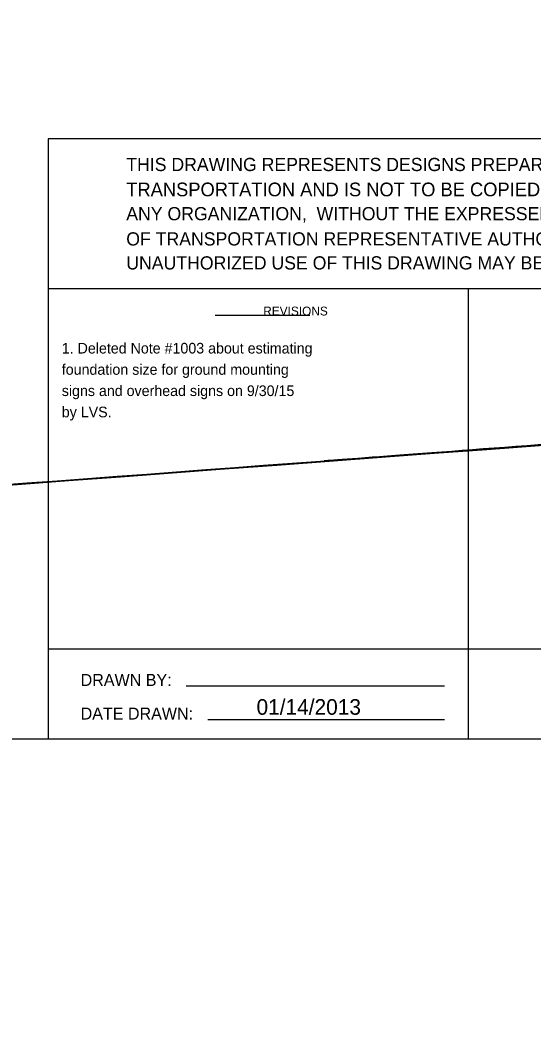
# Model space of a CAD drawing. Extents: x -1.2 to 9.9, y -0.1 to 1.8.
# Drawn here: x 2.1752 to 2.4163, y -0.0886 to 0.3811 of the extents above; entities that cross this region are included whole.
import ezdxf

# ---------------------------------------------------------------- set-up
doc = ezdxf.new("R2010")
doc.units = 0
for name, color, linetype in [('Default', 7, 'Continuous'), ('Level 1', 7, 'Continuous'), ('Level 3', 7, 'Continuous'), ('Level 4', 7, 'Continuous'), ('Level 8', 7, 'Continuous')]:
    doc.layers.add(name, color=color, linetype=linetype)

msp = doc.modelspace()

# ---------------------------------------------------------------- linework, layer by layer
at = {"layer": 'Default'}
msp.add_lwpolyline([(0.06666383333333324, 1.7901942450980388), (0.06666383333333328, 0.04313542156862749), (2.7666638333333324, 0.04313542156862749), (2.7666638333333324, 1.6901942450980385), (2.3666638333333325, 1.690194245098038), (2.3666638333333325, 1.7901942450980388)], close=True, dxfattribs=at)
at = {"layer": 'Level 1'}
for p, q in [((2.1884584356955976, 0.3252695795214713), (2.1884584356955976, 0.04313542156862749)), ((2.7668281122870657, 0.3252695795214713), (2.1884584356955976, 0.3252695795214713)), ((2.2668867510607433, 0.24231905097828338), (2.311467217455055, 0.24231905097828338))]:
    msp.add_line(p, q, dxfattribs=at)
for points in [[(2.1884584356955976, 0.3252695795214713), (2.1884584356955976, 0.04313542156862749)], [(2.7668281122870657, 0.2547322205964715), (2.1884584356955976, 0.2547322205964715)], [(2.385953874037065, 0.04313542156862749), (2.385953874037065, 0.2547322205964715)]]:
    msp.add_lwpolyline(points, dxfattribs=at)
msp.add_spline([(2.4604328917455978, 0.18476013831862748), (2.4609905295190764, 0.18476013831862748), (2.4621210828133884, 0.18476013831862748), (2.4626939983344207, 0.18476013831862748), (2.4626939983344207, 0.18533305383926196), (2.463251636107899, 0.18476013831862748), (2.4649474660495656, 0.18476013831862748), (2.465505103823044, 0.18476013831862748), (2.466078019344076, 0.18476013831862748), (2.4666356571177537, 0.18476013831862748), (2.4666356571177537, 0.18476013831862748), (2.4677662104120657, 0.18476013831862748), (2.4688967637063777, 0.18476013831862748)], degree=3, dxfattribs=at)
at = {"layer": 'Level 3'}
for p, q in [((2.253343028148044, 0.06796176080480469), (2.374663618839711, 0.06796176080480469)), ((2.263502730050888, 0.05216457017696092), (2.374663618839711, 0.05216457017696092))]:
    msp.add_line(p, q, dxfattribs=at)
for points in [[(2.1884584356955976, 0.08545478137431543), (2.385953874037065, 0.08545478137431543)], [(2.385953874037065, 0.08545478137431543), (2.7666638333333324, 0.08545478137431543)]]:
    msp.add_lwpolyline(points, dxfattribs=at)

# ---------------------------------------------------------------- texts
at = {"layer": 'Level 1'}
for s, height, p in [('THIS DRAWING REPRESENTS DESIGNS PREPARED FOR USE BY THE ALABAMA DEPARTMENT OF', 0.006205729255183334, (2.2251326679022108, 0.31003002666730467)), ('TRANSPORTATION AND IS NOT TO BE COPIED,  REPRODUCED,  ALTERED,  OR USED BY ANYONE,  OR', 0.006432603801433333, (2.2251326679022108, 0.29818213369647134)), ('ANY ORGANIZATION,  WITHOUT THE EXPRESSED WRITTEN CONSENT OF THE ALABAMA DEPARTMENT', 0.006205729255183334, (2.2251326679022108, 0.2868995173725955)), ('OF TRANSPORTATION REPRESENTATIVE AUTHORIZED TO APPROVE THIS USE.   ANYONE MAKING', 0.006205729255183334, (2.2251326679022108, 0.2750439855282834)), ('UNAUTHORIZED USE OF THIS DRAWING MAY BE PROSECUTED TO THE FULLEST EXTENT OF THE LAW.', 0.006205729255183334, (2.2251326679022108, 0.2637613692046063)), ('REVISIONS', 0.004166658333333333, (2.2894995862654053, 0.24214204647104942))]:
    msp.add_text(s, height=height, dxfattribs=at).set_placement(p)
at = {"layer": 'Level 3'}
for s, p in [('DRAWN BY:', (2.2036903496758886, 0.06796176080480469)), ('DATE DRAWN:', (2.2036903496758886, 0.05216457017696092))]:
    msp.add_text(s, height=0.005643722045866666, dxfattribs=at).set_placement(p)
at = {"layer": 'Level 4'}
for s, p in [('1. Deleted Note #1003 about estimating', (2.1948292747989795, 0.22426241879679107)), ('foundation size for ground mounting ', (2.1948292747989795, 0.21426243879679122)), ('signs and overhead signs on 9/30/15', (2.1948292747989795, 0.20426245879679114)), ('by LVS.', (2.1948292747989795, 0.19426247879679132))]:
    msp.add_text(s, height=0.00499999, dxfattribs=at).set_placement(p)
at = {"layer": 'Level 8'}
msp.add_text('01/14/2013', height=0.007333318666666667, dxfattribs=at).set_placement((2.2863506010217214, 0.0544256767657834))

doc.saveas('drawing.dxf')
